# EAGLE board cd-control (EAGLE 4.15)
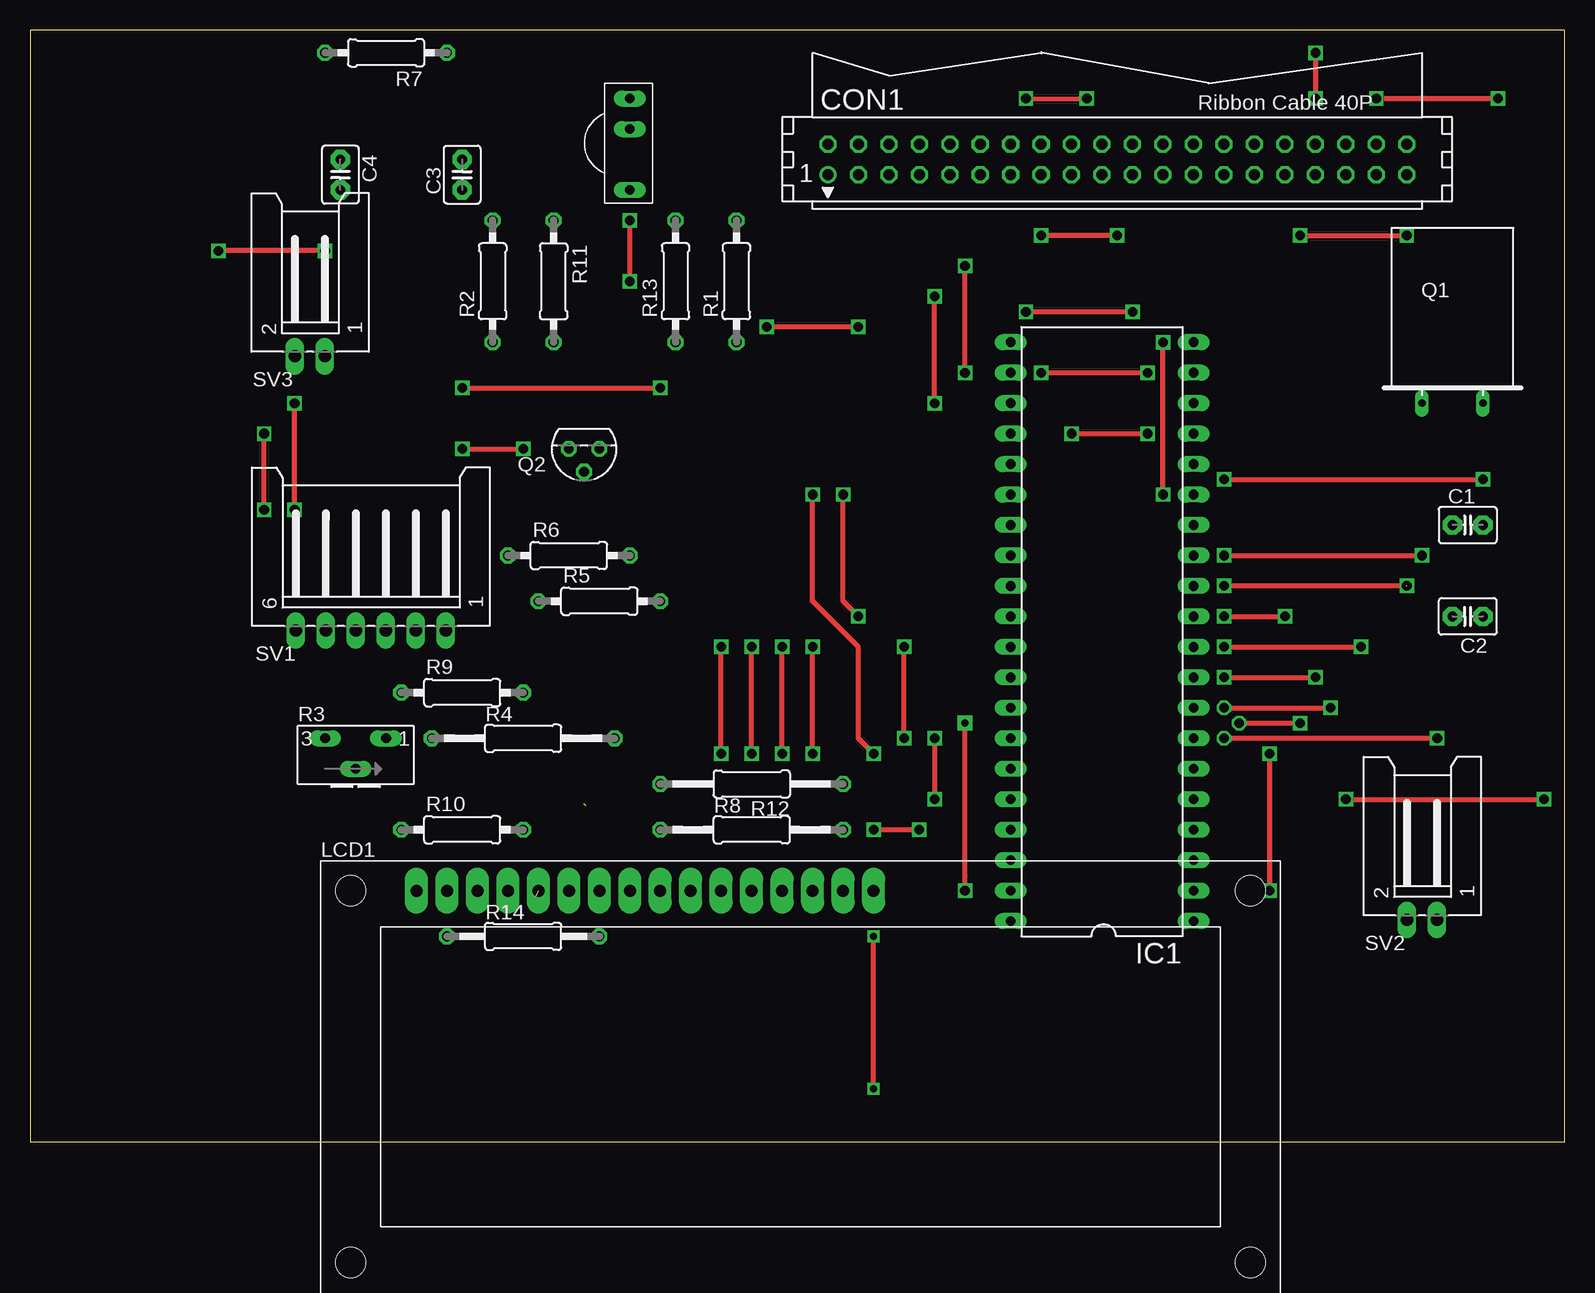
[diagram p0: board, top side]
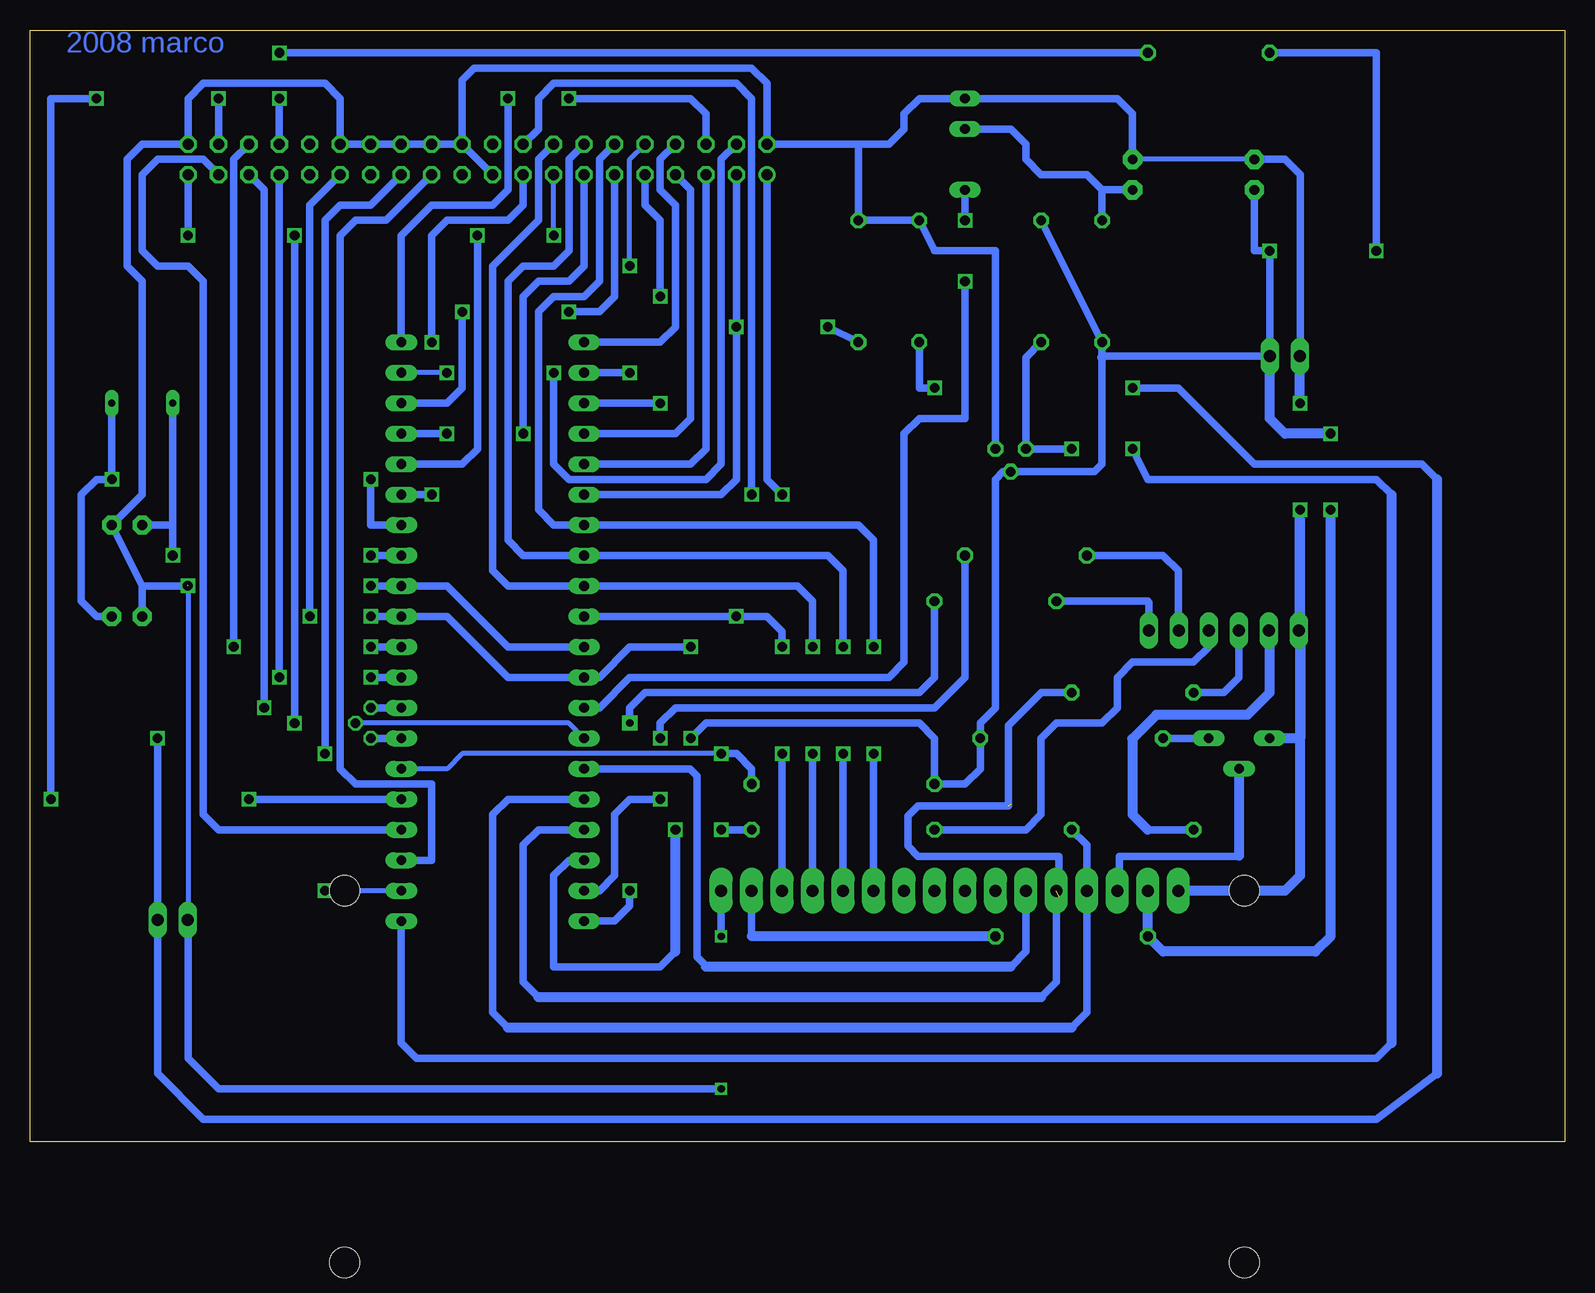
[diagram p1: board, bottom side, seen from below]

Size 127.94 x 92.7 mm. Coordinates in mm from the lower left corner, seen from the top.
Outline: 0,0 127.94,0 127.94,92.7 0,92.7 0,0
Copper layers (1*16): Top 0.035mm / dielectric 1.5mm / Bottom 0.035mm
Design rules "default": minimum track width 10mil, minimum drill 24mil, track to track 8mil, track to pad 8mil, pad to pad 8mil, via to via 8mil, smd to smd 8mil, copper to edge 40mil, drill to drill 8mil, minimum pad ring 10mil, minimum via ring 8mil, stop-mask expansion 4mil, vias tented up to drill 0mil, thermal gap 10mil
Net classes: 0 default: width 0.508 mm, drill 0.381 mm, clearance 0.813 mm

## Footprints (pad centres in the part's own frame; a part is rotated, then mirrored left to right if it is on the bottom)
C2.5-3 = drill 0.813 pad 1.6 octagon: 1 -1.27,0; 2 1.27,0
CON40 = drill 0.914 round: 1 -24.13,-1.27 | drill 0.914 octagon: 2 -24.13,1.27; 3 -21.59,-1.27; 4 -21.59,1.27; 5 -19.05,-1.27; 6 -19.05,1.27; 7 -16.51,-1.27; 8 -16.51,1.27; 9 -13.97,-1.27; 10 -13.97,1.27; 11 -11.43,-1.27; 12 -11.43,1.27; 13 -8.89,-1.27; 14 -8.89,1.27; 15 -6.35,-1.27; 16 -6.35,1.27; 17 -3.81,-1.27; 18 -3.81,1.27; 19 -1.27,-1.27; 20 -1.27,1.27; 21 1.27,-1.27; 22 1.27,1.27; 23 3.81,-1.27; 24 3.81,1.27; 25 6.35,-1.27; 26 6.35,1.27; 27 8.89,-1.27; 28 8.89,1.27; 29 11.43,-1.27; 30 11.43,1.27; 31 13.97,-1.27; 32 13.97,1.27; 33 16.51,-1.27; 34 16.51,1.27; 35 19.05,-1.27; 36 19.05,1.27; 37 21.59,-1.27; 38 21.59,1.27; 39 24.13,-1.27; 40 24.13,1.27
DIL40 = drill 0.813 long: 1 -24.13,-7.62; 2 -21.59,-7.62; 3 -19.05,-7.62; 4 -16.51,-7.62; 5 -13.97,-7.62; 6 -11.43,-7.62; 7 -8.89,-7.62; 8 -6.35,-7.62; 9 -3.81,-7.62; 10 -1.27,-7.62; 11 1.27,-7.62; 12 3.81,-7.62; 13 6.35,-7.62; 14 8.89,-7.62; 15 11.43,-7.62; 16 13.97,-7.62; 17 16.51,-7.62; 18 19.05,-7.62; 19 21.59,-7.62; 20 24.13,-7.62; 21 24.13,7.62; 22 21.59,7.62; 23 19.05,7.62; 24 16.51,7.62; 25 13.97,7.62; 26 11.43,7.62; 27 8.89,7.62; 28 6.35,7.62; 29 3.81,7.62; 30 1.27,7.62; 31 -1.27,7.62; 32 -3.81,7.62; 33 -6.35,7.62; 34 -8.89,7.62; 35 -11.43,7.62; 36 -13.97,7.62; 37 -16.51,7.62; 38 -19.05,7.62; 39 -21.59,7.62; 40 -24.13,7.62
HY-1602F = drill 1 pad 1.93 long: 1 2.54,0; 2 5.08,0; 3 7.62,0; 4 10.16,0; 5 12.7,0; 6 15.24,0; 7 17.78,0; 8 20.32,0; 9 22.86,0; 10 25.4,0; 11 27.94,0; 12 30.48,0; 13 33.02,0; 14 35.56,0; 15 38.1,0; 16 40.64,0 | hole 2.5: -2.96,0; 72.04,0; -2.96,-31; 72.04,-31
Q = drill 0.61 long: 1 -2.54,-7.62; 2 2.54,-7.62
TO92 = drill 0.813 octagon: 1 1.27,0; 2 0,1.905; 3 -1.27,0
0207/10 = drill 0.813 octagon: 1 -5.08,0; 2 5.08,0
S63X = drill 0.813 long: A 2.54,0; E -2.54,0; S 0,-2.54
0207/15 = drill 0.813 octagon: 1 -7.62,0; 2 7.62,0
0207/12 = drill 0.813 octagon: 1 -6.35,0; 2 6.35,0
L06P = drill 1.016 long: 1 6.25,-6.25; 2 3.75,-6.25; 3 1.25,-6.25; 4 -1.25,-6.25; 5 -3.75,-6.25; 6 -6.25,-6.25
L02P = drill 1.016 long: 1 1.25,-6.25; 2 -1.25,-6.25
TSOP17XX = drill 0.813 long: GND -3.81,0; OUT 3.81,0; V+ -1.27,0

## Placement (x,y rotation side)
C1  47p  [C2.5-3]  119.85,51.43 0 top
C2  47p  [C2.5-3]  119.85,43.81 180 top
C3  4.7uF  [C2.5-3]  36.03,80.64 90 top
C4  4.7uF  [C2.5-3]  25.87,80.64 270 top
CON1  [CON40]  90.64,81.91 0 top
IC1  [DIL40]  89.37,42.54 90 top
LCD1  LCD_2X16_SIL  [HY-1602F]  29.68,20.95 0 top
Q1  [Q]  118.58,69.21 0 top
Q2  mcp120d  [TO92]  46.19,57.78 180 top
R1  10k  [0207/10]  58.89,71.75 90 top
R2  100r  [0207/10]  38.57,71.75 90 top
R3  5k  [S63X]  27.14,33.65 0 top
R4  15k  [0207/15]  41.11,33.65 0 top
R5  1k  [0207/10]  47.46,45.08 0 top
R6  1k  [0207/10]  44.92,48.89 0 top
R7  1k  [0207/10]  29.68,90.8 180 top
R8  1k  [0207/15]  60.16,26.03 0 top
R9  1k  [0207/10]  36.03,37.46 0 top
R10  1k  [0207/10]  36.03,26.03 0 top
R11  10k  [0207/10]  43.65,71.75 270 top
R12  10k  [0207/15]  60.16,29.84 180 top
R13  10k  [0207/10]  53.81,71.75 90 top
R14  500r  [0207/12]  41.11,17.14 0 top
SV1  [L06P]  28.41,48.89 0 top
SV2  stand-by  [L02P]  116.04,24.76 0 top
SV3  power  [L02P]  23.33,71.75 0 top
U$1  TSOP1736  [TSOP17XX]  50,83.18 270 top

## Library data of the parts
C1-C4 = capacitor-wima
CON1 = con-harting
IC1 = ic-package
LCD1 = lcd_2x16_led_backlight
Q1 = special
Q2 = transistor-pnp
R1 R2 R4-R14 = rcl
R3 = pot
SV1-SV3 = con-amp-mt
U$1 = tsop

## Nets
BUT1: IC1.40 R5.2
BUT2: IC1.39 R6.2
BUT3: IC1.38 R8.2
BUT4: IC1.37 LCD1.5 R9.2
BUT5: IC1.36 LCD1.4 R10.2
CS0: CON1.37 IC1.4
CS1: CON1.38 IC1.5
DA0: CON1.35 IC1.8
DA1: CON1.33 IC1.9
DA2: CON1.36 IC1.10
DASP: CON1.39 IC1.34
DD0: CON1.17 IC1.15
DD1: CON1.15 IC1.16
DD2: CON1.13 IC1.17
DD3: CON1.11 IC1.18
DD4: CON1.9 IC1.23
DD5: CON1.7 IC1.24
DD6: CON1.5 IC1.25
DD7: CON1.3 IC1.26 R1.1
DD8: CON1.4 IC1.19
DD9: CON1.6 IC1.20
DD10: CON1.8 IC1.21
DD11: CON1.10 IC1.22
DD12: CON1.12 IC1.27 LCD1.11
DD13: CON1.14 IC1.28 LCD1.12
DD14: CON1.16 IC1.29 LCD1.13
DD15: CON1.18 IC1.30 LCD1.14
DIOR: CON1.25 IC1.2
DIOW: CON1.23 IC1.3
IRED: IC1.33 U$1.OUT
LCDE: IC1.35 LCD1.6
N$1: C3.1 R2.2 U$1.V+
N$2: IC1.1 Q2.1 R11.2
N$3: R5.1 SV1.1
N$4: LCD1.3 R3.S
N$5: R3.A R4.1
N$6: R6.1 SV1.2
N$7: C1.1 IC1.13 Q1.1
N$8: C2.1 IC1.14 Q1.2
N$9: CON1.34 R7.1
N$10: R8.1 SV1.3
N$11: R9.1 SV1.4
N$12: R10.1 SV1.5
N$14: IC1.7 R13.1 SV2.1
PE: C1.2 C2.2 C3.2 C4.1 CON1.2 CON1.19 CON1.22 CON1.24 CON1.26 CON1.28 CON1.30 CON1.40 IC1.12 IC1.31 LCD1.1 Q2.3 R1.2 R3.E R13.2 SV1.6 SV2.2 SV3.2 U$1.GND
RESET: CON1.1 IC1.6 R12.1
S$1: LCD1.16
S$3: LCD1.15
VCC: C4.2 CON1.29 IC1.11 IC1.32 LCD1.2 Q2.2 R2.1 R4.2 R7.2 R11.1 R12.2 SV3.1

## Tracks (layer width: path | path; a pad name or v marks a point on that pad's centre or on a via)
BUT1  (via drill 0.6 pad 1.27, 0.8)
  Top 0.406: 77.94,22.22 v77.94,20.95 v77.94,34.92
  Bottom 0.61: R5.2 52.54,38.73 53.81,37.46 76.67,37.46 77.94,36.19 v77.94,34.92 | IC1.40 79.21,18.41 77.94,19.68 v77.94,20.95
BUT2  (via drill 0.8)
  Top 0.406: v75.4,33.65 v75.4,28.57
  Bottom 0.406: IC1.39 80.48,20.95
  Bottom 0.61: v75.4,33.65 75.4,34.92 74.13,36.19 52.54,36.19 50,38.73 R6.2 | v75.4,28.57 77.94,28.57 79.21,27.3 79.21,22.22 80.48,20.95
BUT3  (via drill 0.8)
  Top 0.406: v74.13,26.03 v70.32,26.03
  Bottom 0.61: v70.32,26.03 R8.2 | 74.13,15.87 75.4,14.6 84.29,14.6 84.29,22.22 83.02,23.49 IC1.38
  Bottom 0.813: 74.13,15.87 v74.13,26.03
BUT4  (2 unrouted)
  Bottom 0.61: IC1.37 85.56,26.03 86.83,24.76 86.83,13.33 85.56,12.06 | 43.65,12.06 42.38,13.33 42.38,20.26 42.18,20.47 42.18,23.82 53.91,23.82 54.75,24.66 54.75,27.17 53.91,28.01 46.37,28.01 46.37,34.72 43.62,37.46 R9.2
  Bottom 0.813: 43.65,12.06 85.56,12.06
BUT5
  Bottom 0.61: IC1.36 88.1,28.57 89.37,27.3 89.37,10.79 88.1,9.52 | 41.11,9.52 39.84,10.79 LCD1.4 39.84,24.76 R10.2
  Bottom 0.813: 41.11,9.52 88.1,9.52
CS0
  Bottom 0.61: CON1.37 113.5,81.91 117.31,81.91 118.58,80.64 118.58,74.29 117.31,73.02 114.77,73.02 113.5,71.75 113.5,27.3 112.23,26.03 IC1.4
CS1  (via drill 0.8)
  Top 0.406: v109.69,28.57 v126.2,28.57 | v122.39,86.99 v112.23,86.99
  Bottom 0.61: IC1.5 v109.69,28.57 | v112.23,86.99 CON1.38 | v122.39,86.99 126.2,86.99 v126.2,28.57
DA0  (via drill 0.8)
  Top 0.406: v99.53,36.19 v108.42,36.19
  Bottom 0.61: CON1.35 108.42,79.37 v108.42,36.19 | IC1.8 v99.53,36.19
DA1  (via drill 0.8)
  Top 0.406: v99.53,38.73 v107.15,38.73
  Bottom 0.61: v107.15,38.73 CON1.33 | IC1.9 v99.53,38.73
DA2  (via drill 0.8)
  Top 0.406: v99.53,41.27 v110.96,41.27
  Bottom 0.61: CON1.36 110.96,81.91 v110.96,41.27 | IC1.10 v99.53,41.27
DASP  (via drill 0.8)
  Top 0.406: v100.8,34.92 v105.88,34.92 | v105.88,75.56 v114.77,75.56
  Bottom 0.406: v100.8,34.92 83.02,34.92 IC1.34
  Bottom 0.61: v114.77,75.56 CON1.39 | v105.88,34.92 v105.88,75.56
DD0  (via drill 0.8)
  Top 0.406: v94.45,53.97 v94.45,66.67
  Bottom 0.61: v94.45,66.67 94.45,75.56 93.18,76.83 88.1,76.83 86.83,78.1 CON1.17 | v94.45,53.97 IC1.15
DD1  (via drill 0.8)
  Top 0.406: v90.64,75.56 v84.29,75.56
  Bottom 0.406: v84.29,75.56 CON1.15
  Bottom 0.61: IC1.16 91.91,56.51 90.64,57.78 v90.64,75.56
DD2  (via drill 0.8)
  Top 0.406: v86.83,59.05 v93.18,59.05
  Bottom 0.61: CON1.13 81.75,73.02 83.02,71.75 85.56,71.75 86.83,70.48 v86.83,59.05 | v93.18,59.05 IC1.17
DD3  (via drill 0.8)
  Top 0.406: v83.02,69.21 v91.91,69.21
  Bottom 0.61: CON1.11 79.21,70.48 80.48,69.21 v83.02,69.21 | IC1.18 93.18,61.59 91.91,62.86 v91.91,69.21
DD4  (via drill 0.8)
  Top 0.406: v75.4,61.59 v75.4,70.48
  Bottom 0.61: v75.4,61.59 IC1.23 | CON1.9 76.67,78.1 75.4,76.83 v75.4,70.48
DD5
  Bottom 0.61: CON1.7 72.86,79.37 72.86,60.32 74.13,59.05 IC1.24
DD6
  Bottom 0.61: CON1.5 71.59,57.78 72.86,56.51 IC1.25
DD7  (via drill 0.8)
  Top 0.406: v69.05,67.94 v61.43,67.94
  Bottom 0.61: IC1.26 70.32,53.97 69.05,55.24 v69.05,67.94 CON1.3 | v61.43,67.94 R1.1
DD8  (via drill 0.8)
  Top 0.406: v84.29,64.13 v93.18,64.13
  Bottom 0.406: v93.18,64.13 IC1.19
  Bottom 0.61: CON1.4 70.32,81.91 70.32,56.51 71.59,55.24 83.02,55.24 84.29,56.51 v84.29,64.13
DD9  (via drill 0.8)
  Top 0.406: v83.02,86.99 v88.1,86.99
  Bottom 0.61: IC1.20 96.99,75.56 94.45,78.1 89.37,78.1 88.1,79.37 v88.1,86.99 | CON1.6 71.59,85.72 72.86,86.99 v83.02,86.99
DD10
  Bottom 0.61: CON1.8 75.4,81.91 75.4,79.37 74.13,78.1 74.13,67.94 75.4,66.67 IC1.21
DD11  (via drill 0.8)
  Top 0.406: v77.94,64.13 v77.94,73.02
  Bottom 0.406: CON1.10 77.94,81.91 v77.94,73.02
  Bottom 0.61: v77.94,64.13 IC1.22
DD12  (via drill 0.8)
  Top 0.406: v57.62,32.38 v57.62,41.27
  Bottom 0.61: CON1.12 80.48,81.91 80.48,71.75 81.75,70.48 84.29,70.48 85.56,69.21 85.56,52.7 84.29,51.43 IC1.27 58.89,51.43 57.62,50.16 v57.62,41.27 | LCD1.11 v57.62,32.38
DD13  (via drill 0.8)
  Top 0.406: v60.16,32.38 v60.16,41.27
  Bottom 0.61: CON1.14 83.02,81.91 83.02,74.29 84.29,73.02 86.83,73.02 88.1,71.75 88.1,50.16 86.83,48.89 IC1.28 61.43,48.89 60.16,47.62 v60.16,41.27 | LCD1.12 v60.16,32.38
DD14  (via drill 0.8)
  Top 0.406: v62.7,32.38 v62.7,41.27
  Bottom 0.406: 72.86,46.35 71.59,46.35
  Bottom 0.61: CON1.16 85.56,81.91 85.56,76.83 89.37,73.02 89.37,47.62 88.1,46.35 IC1.29 72.86,46.35 63.97,46.35 62.7,45.08 v62.7,41.27 | LCD1.13 v62.7,32.38
DD15  (via drill 0.8)
  Top 0.406: v67.78,53.97 67.78,45.08 v69.05,43.81 | v65.24,32.38 v65.24,41.27
  Bottom 0.406: v69.05,43.81 IC1.30
  Bottom 0.61: v67.78,53.97 67.78,86.99 69.05,88.26 84.29,88.26 85.56,86.99 85.56,84.45 CON1.18 | LCD1.14 v65.24,32.38 | IC1.30 v69.05,43.81 66.51,43.81 65.24,42.54 v65.24,41.27
DIOR  (via drill 0.8)
  Top 0.406: v103.34,20.95 v103.34,32.38
  Bottom 0.406: IC1.2 v103.34,20.95
  Bottom 0.61: CON1.25 99.53,78.1 102.07,78.1 103.34,76.83 v103.34,32.38
DIOW
  Bottom 0.61: IC1.3 94.45,23.49 94.45,29.84 100.8,29.84 102.07,31.11 102.07,75.56 100.8,76.83 98.26,76.83 CON1.23
IRED  (via drill 0.8)
  Top 0.406: v50,71.75 v50,76.83
  Bottom 0.406: 80.48,36.19 IC1.33
  Bottom 0.61: v50,71.75 50,60.32 53.81,60.32 55.08,59.05 55.08,40 56.35,38.73 77.94,38.73 80.48,36.19 | v50,76.83 U$1.OUT
LCDE
  Bottom 0.61: 46.19,14.6 44.92,15.87 LCD1.6 | 71.59,14.6 71.59,14.68 72.35,15.44 72.35,30.53 72.94,31.11 IC1.35
  Bottom 0.813: 46.19,14.6 71.59,14.6
N$1
  Bottom 0.61: 38.57,79.37 C3.1 | 38.57,79.37 39.84,80.64 43.65,80.64 44.92,81.91 44.92,83.18 46.19,84.45 U$1.V+ | R2.2 38.57,79.37
N$2  (via drill 0.8)
  Top 0.406: v36.03,57.78 v41.11,57.78
  Bottom 0.61: v36.03,57.78 34.76,55.24 15.71,55.24 14.44,53.97 | v41.11,57.78 Q2.1 44.92,65.4 R11.2 | 14.44,8.25 15.71,6.98 95.72,6.98 96.99,8.25 IC1.1
  Bottom 0.813: 14.44,8.25 14.44,53.97
N$3
  Bottom 0.406: 34.66,44.98 34.76,45.08
  Bottom 0.61: SV1.1 34.66,44.98 | 34.76,45.08 R5.1
N$4
  Bottom 0.61: 27.14,23.87 27.09,23.82 37.15,23.82 37.15,20.47 37.3,20.62 LCD1.3
  Bottom 0.813: 27.14,23.87 R3.S
N$5
  Bottom 0.61: R3.A R4.1
N$6
  Bottom 0.406: 32.22,42.54 32.16,42.6 SV1.2
  Bottom 0.61: R6.1 33.49,48.89 32.22,47.62 32.22,42.54
N$7  (via drill 0.8)
  Top 0.406: v99.53,48.89 v116.04,48.89
  Bottom 0.61: 116.04,51.43 C1.1 | v116.04,48.89 116.04,51.43 | 116.04,51.43 Q1.1 | IC1.13 v99.53,48.89
N$8  (via drill 0.8)
  Top 0.406: v99.53,55.24 v121.12,55.24
  Bottom 0.61: IC1.14 99.53,51.43 v99.53,55.24 | Q1.2 v121.12,55.24 122.39,55.24 123.66,53.97 123.66,45.08 122.39,43.81 C2.1
N$9  (via drill 0.8)
  Top 0.406: v107.15,90.8 v107.15,86.99
  Bottom 0.61: v107.15,86.99 CON1.34 | R7.1 v107.15,90.8
N$10
  Bottom 0.406: SV1.3 29.68,42.62 29.68,41.27
  Bottom 0.61: 29.68,41.27 30.95,40 36.03,40 37.3,38.73 37.3,36.19 38.57,34.92 42.38,34.92 43.65,33.65 43.65,27.3 44.92,26.03 R8.1
N$11
  Bottom 0.61: SV1.4 27.16,38.73 28.43,37.46 R9.1
N$12
  Bottom 0.406: 24.6,42.54 24.66,42.6 SV1.5
  Bottom 0.61: R10.1 34.76,26.03 | 36.03,33.65 36.03,33.6 36.06,33.6
  Bottom 0.813: 24.6,42.54 24.6,37.46 26.46,35.6 34.06,35.6 36.06,33.6 | 34.76,26.03 36.03,27.3 36.03,33.6
N$14  (via drill 0.8)
  Top 0.406: v36.03,62.86 v52.54,62.86 | v117.31,33.65 v99.53,33.65
  Bottom 0.406: v99.53,33.65 IC1.7 | 117.31,27.38 117.31,27.3 | 117.31,18.41 117.29,18.43 SV2.1
  Bottom 0.61: SV2.1 117.31,27.38 v117.31,33.65 | v99.53,33.65 IC1.7 | R13.1 53.81,62.86 v52.54,62.86 | v36.03,62.86 32.22,62.86 25.87,56.51 11.9,56.51 10.63,55.24 | 117.31,18.41 117.31,5.71 113.5,1.9 15.71,1.9 10.63,5.71
  Bottom 0.813: 10.63,5.71 10.63,55.24
N$18  (via drill 0.8)
  other vias: 22.06,61.59
PE  (via drill 0.8)  (1 unrouted)
  Top 0.406: v22.06,52.7 v22.06,61.59 | v114.79,46.37 99.55,46.37 v99.53,46.35
  Bottom 0.406: SV1.6 22.16,33.75 22.06,33.65 | 22.06,51.43 v22.06,52.7 | C4.1 C3.2 | SV3.2 22.06,65.4 | SV2.2 114.77,18.51 v114.77,46.35
  Bottom 0.61: CON1.22 91.91,88.53 90.91,89.53 67.78,89.53 66.51,88.26 CON1.2 58.89,83.18 | CON1.22 CON1.19 | IC1.31 88.1,41.27 93.18,46.35 IC1.12 v99.53,46.35 | 118.58,46.35 C1.2 118.58,53.97 118.58,71.75 119.85,73.02 119.85,81.91 118.58,83.18 CON1.40 114.77,86.99 113.5,88.26 103.34,88.26 102.07,86.99 CON1.30 CON1.28 CON1.26 CON1.24 CON1.22 | 118.58,46.35 C2.2 | 118.58,46.35 v114.77,46.35 | 58.89,83.18 56.35,83.18 55.08,84.45 55.08,85.72 53.81,86.99 U$1.GND 37.3,86.99 36.03,85.72 C3.2 | 58.89,83.18 R1.2 R13.2 52.54,74.29 47.46,74.29 Q2.3 | 22.06,65.4 22.06,80.64 23.33,81.91 C4.1
  Bottom 0.813: 22.06,43.81 22.08,43.83 22.08,52.68 22.06,51.43 22.06,43.81 | SV3.2 22.08,61.61 v22.06,61.59 | 22.06,42.54 SV1.6 | 22.06,42.54 22.06,43.81 | R3.E 22.06,33.65 22.06,42.54 | 22.06,42.54 22.06,22.22 23.33,20.95 LCD1.1
RESET  (via drill 0.8)
  Top 0.406: v65.24,53.97 65.24,45.08 69.05,41.27 69.05,33.65 v70.32,32.38
  Bottom 0.406: v70.32,32.38 91.91,32.38 93.18,31.11 IC1.6
  Bottom 0.61: R12.1 67.78,31.11 69.05,32.38 v70.32,32.38 | CON1.1 66.51,55.24 v65.24,53.97
S$1  (via drill 0.6)
  Top 0.406: v70.32,4.44 v70.32,17.14
  Bottom 0.61: v70.32,17.14 LCD1.16 | v70.32,4.44 112.23,4.44 114.77,6.98 114.77,18.41
S$3  (via drill 0.7 pad 1.27)
  Bottom 0.61: 67.78,17.14 LCD1.15
  Bottom 0.813: v47.46,17.14 67.78,17.14
VCC  (via drill 0.7 pad 1.27, 0.8)
  Top 0.406: v72.86,33.65 v72.86,41.27 | v19.52,52.7 v19.52,59.05 | v24.6,74.29 v15.71,74.29 | v99.53,43.81 v104.61,43.81
  Bottom 0.406: Q2.2 46.83,55.88 | 80.48,38.73 IC1.32 | 24.58,74.27 v24.6,74.29 | 24.6,65.4 24.7,65.5
  Bottom 0.61: IC1.32 88.1,38.73 93.18,43.81 IC1.11 v99.53,43.81 | CON1.29 104.61,78.1 v104.61,43.81 | Q2.2 39.2,55.88 38.57,56.51 38.57,65.4 R2.1 R11.1 | v72.86,33.65 71.59,34.92 53.81,34.92 52.54,33.65 R12.2 50,29.84 48.73,31.11 R4.2 48.73,34.92 47.46,36.19 47.46,55.24 46.83,55.88 | v72.86,41.27 77.94,41.27 80.48,38.73 | SV3.1 24.58,74.27 | v15.71,74.29 15.71,90.8 R7.2 | C4.2 25.87,74.29 v24.6,74.29 | 24.7,65.5 38.47,65.5
  Bottom 0.813: 38.47,65.5 38.57,65.4 | LCD1.2 v34.76,17.14 33.49,15.87 20.79,15.87 19.52,17.14 v19.52,52.7 | SV3.1 24.58,65.42 24.6,65.4 24.6,60.32 23.33,59.05 v19.52,59.05

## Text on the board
Bottom: 2008 marco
